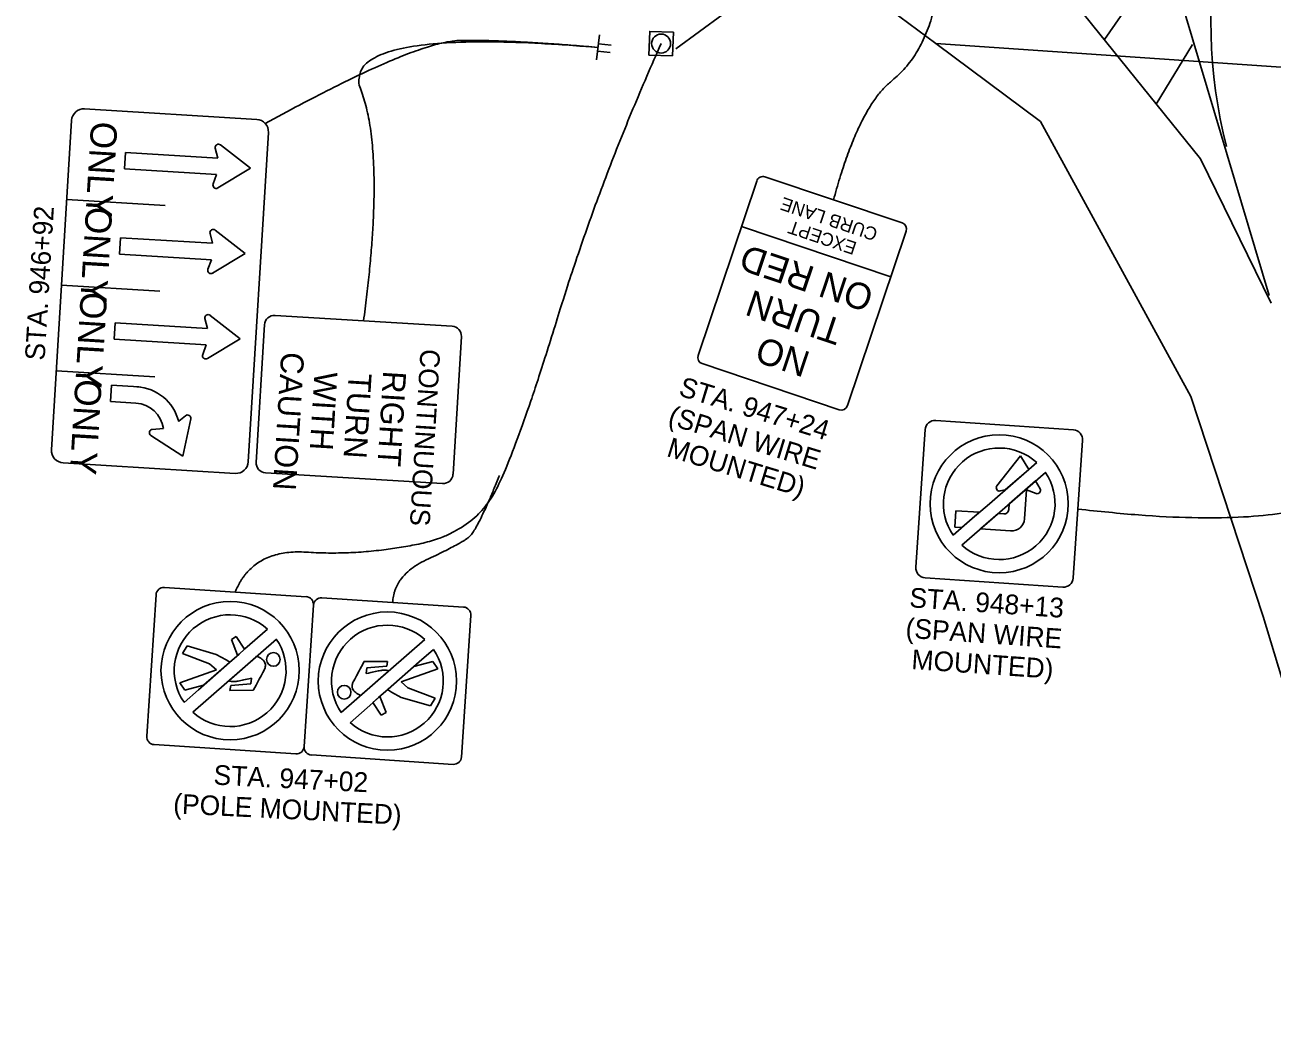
# Model space of a CAD drawing. Extents: x 1847379 to 1850904, y 217032 to 220169.
# Drawn here: x 1848753.2 to 1848911.4, y 218673.2 to 218799.7 of the extents above; entities that cross this region are included whole.
import ezdxf

# ---------------------------------------------------------------- set-up
doc = ezdxf.new("R2010")
doc.units = 0
for name, color, linetype in [('BR_P_Gen_Approach_Slab_Hidden', 7, 'Continuous'), ('BR_P_Gen_Phase_Construction', 7, 'Continuous'), ('PM_P_Channelizing_Line', 7, 'Continuous'), ('PM_P_Dotted_Line', 7, 'Continuous'), ('PM_P_Edge_Line', 7, 'Continuous'), ('PM_P_Transverse_Line', 7, 'Continuous'), ('SG_X_Wiring', 7, 'Continuous'), ('SN_X_Foundation', 7, 'Continuous'), ('SN_X_Public', 7, 'Continuous'), ('SN_X_Text', 7, 'Continuous')]:
    doc.layers.add(name, color=color, linetype=linetype)

msp = doc.modelspace()

# ---------------------------------------------------------------- linework, layer by layer
at = {"layer": 'BR_P_Gen_Approach_Slab_Hidden'}
for p, q in [((1848868.73, 218797.37), (1848882.03, 218787.46)), ((1848882.03, 218787.46), (1848901.06, 218752.58)), ((1848901.06, 218752.58), (1848910.26, 218724.65)), ((1848910.26, 218724.65), (1848925.73, 218673.2))]:
    msp.add_line(p, q, dxfattribs=at)
at = {"layer": 'BR_P_Gen_Phase_Construction'}
msp.add_line((1848868.73, 218797.37), (1848933.64, 218792.93), dxfattribs=at)
at = {"layer": 'PM_P_Channelizing_Line'}
msp.add_lwpolyline([(1848911.03, 218765.37), (1848897.81, 218809.62), (1848893.91, 218821.93), (1848835.25, 218825.52), (1848857.61, 218820.78), (1848883.89, 218805.62), (1848902.29, 218782.73), (1848911.26, 218764.42)], dxfattribs=at)
at = {"layer": 'PM_P_Dotted_Line'}
msp.add_arc((1848965.57, 218799.82), 61.94, 89.125, 194.5243, dxfattribs=at)
at = {"layer": 'PM_P_Edge_Line'}
msp.add_line((1848858.25, 218805.17), (1848868.73, 218797.37), dxfattribs=at)
at = {"layer": 'PM_P_Transverse_Line'}
for p, q in [((1848897.69, 218808.79), (1848890.12, 218797.86)), ((1848896.7, 218789.68), (1848901.29, 218797.25))]:
    msp.add_line(p, q, dxfattribs=at)
at = {"layer": 'SG_X_Wiring'}
msp.add_line((1848847.49, 218805.29), (1848835.76, 218796.68), dxfattribs=at)
at = {"layer": 'SN_X_Foundation'}
msp.add_lwpolyline([(1848835.36, 218795.8), (1848835.47, 218798.79), (1848832.47, 218798.9), (1848832.36, 218795.9)], close=True, dxfattribs=at)
msp.add_circle((1848833.91, 218797.35), 1.2, dxfattribs=at)
at = {"layer": 'SN_X_Public'}
for p, q in [((1848825.73, 218795.28), (1848826.11, 218798.46)), ((1848825.86, 218796.39), (1848827.45, 218796.2)), ((1848825.92, 218796.87), (1848825.92, 218796.87)), ((1848825.98, 218797.34), (1848827.56, 218797.15)), ((1848766, 218783.53), (1848765.87, 218781.45)), ((1848777.68, 218782.82), (1848766, 218783.53)), ((1848777.37, 218784.07), (1848777.68, 218782.82)), ((1848781.84, 218781.53), (1848778.03, 218784.5)), ((1848765.87, 218781.45), (1848777.55, 218780.74)), ((1848777.55, 218780.74), (1848777.1, 218779.54)), ((1848777.7, 218779.03), (1848781.84, 218781.53)), ((1848758.54, 218777.57), (1848771.02, 218776.81)), ((1848844.09, 218774.14), (1848863.05, 218767.77)), ((1848765.34, 218772.72), (1848765.22, 218770.64)), ((1848777.02, 218772.01), (1848765.34, 218772.72)), ((1848776.71, 218773.26), (1848777.02, 218772.01)), ((1848781.18, 218770.71), (1848777.37, 218773.69)), ((1848765.22, 218770.64), (1848776.9, 218769.93)), ((1848776.9, 218769.93), (1848776.44, 218768.73)), ((1848777.04, 218768.22), (1848781.18, 218770.71)), ((1848757.88, 218766.7), (1848770.36, 218765.94)), ((1848764.69, 218761.91), (1848764.56, 218759.83)), ((1848776.37, 218761.2), (1848764.69, 218761.91)), ((1848776.06, 218762.45), (1848776.37, 218761.2)), ((1848780.53, 218759.9), (1848776.72, 218762.87)), ((1848764.56, 218759.83), (1848776.24, 218759.12)), ((1848776.38, 218757.41), (1848780.53, 218759.9)), ((1848776.24, 218759.12), (1848775.78, 218757.91)), ((1848757.22, 218755.84), (1848769.7, 218755.08)), ((1848764.08, 218751.92), (1848764.21, 218754)), ((1848764.21, 218754), (1848767.7, 218753.79)), ((1848767.7, 218753.79), (1848767.43, 218753.81)), ((1848767.31, 218751.73), (1848764.08, 218751.92)), ((1848772.74, 218749.43), (1848773.59, 218750.14)), ((1848774.27, 218749.73), (1848773.26, 218745)), ((1848773.26, 218745), (1848769.2, 218747.64)), ((1848769.39, 218748.4), (1848770.79, 218748.53)), ((1848876.49, 218741.25), (1848879.5, 218745.04)), ((1848879.5, 218745.04), (1848876.49, 218741.25)), ((1848880.52, 218743.32), (1848879.5, 218745.04)), ((1848880.52, 218743.32), (1848879.5, 218745.04)), ((1848882.63, 218742.95), (1848872.03, 218733.71)), ((1848877.55, 218740.73), (1848880.52, 218743.32)), ((1848881.38, 218741.86), (1848878.04, 218738.94)), ((1848881.96, 218740.88), (1848881.38, 218741.86)), ((1848881.96, 218740.88), (1848881.38, 218741.86)), ((1848876.92, 218740.59), (1848877.54, 218740.74)), ((1848876.92, 218740.59), (1848877.54, 218740.74)), ((1848880, 218737.07), (1848880.25, 218740.74)), ((1848880, 218737.07), (1848880.25, 218740.74)), ((1848881.45, 218740.28), (1848880.25, 218740.74)), ((1848880.25, 218740.74), (1848881.45, 218740.28)), ((1848871.15, 218736), (1848871.3, 218738.08)), ((1848871.3, 218738.08), (1848871.15, 218736)), ((1848874.28, 218737.88), (1848871.3, 218738.08)), ((1848874.28, 218737.88), (1848871.3, 218738.08)), ((1848873.37, 218737.09), (1848874.28, 218737.88)), ((1848876.63, 218737.72), (1848874.47, 218735.83)), ((1848877.35, 218737.67), (1848876.63, 218737.72)), ((1848877.35, 218737.67), (1848876.63, 218737.72)), ((1848877.99, 218738.22), (1848878.04, 218738.94)), ((1848878.04, 218738.94), (1848877.99, 218738.22)), ((1848872.06, 218735.94), (1848873.37, 218737.09)), ((1848872.06, 218735.94), (1848871.15, 218736)), ((1848871.15, 218736), (1848872.06, 218735.94)), ((1848874.47, 218735.83), (1848874.41, 218735.78)), ((1848878.22, 218735.52), (1848874.41, 218735.78)), ((1848874.41, 218735.78), (1848878.22, 218735.52)), ((1848780.04, 218722.12), (1848779.43, 218721.76)), ((1848780.04, 218722.12), (1848779.43, 218721.76)), ((1848781.09, 218720.51), (1848780.04, 218722.12)), ((1848781.09, 218720.51), (1848780.04, 218722.12)), ((1848773.79, 218720.94), (1848773.21, 218719.95)), ((1848773.79, 218720.94), (1848773.21, 218719.95)), ((1848777.5, 218719.86), (1848773.79, 218720.94)), ((1848777.5, 218719.86), (1848773.79, 218720.94)), ((1848785.12, 218721.79), (1848774.52, 218712.52)), ((1848779.43, 218721.76), (1848780.21, 218719.74)), ((1848779.43, 218721.76), (1848780.21, 218719.74)), ((1848793.34, 218712.46), (1848803.94, 218721.74)), ((1848773.21, 218719.95), (1848776.66, 218718.67)), ((1848773.21, 218719.95), (1848776.66, 218718.67)), ((1848775.89, 218715.95), (1848779.17, 218718.83)), ((1848776.66, 218718.67), (1848777.52, 218717.9)), ((1848776.66, 218718.67), (1848777.52, 218717.9)), ((1848778.74, 218719.18), (1848777.5, 218719.86)), ((1848778.74, 218719.18), (1848777.5, 218719.86)), ((1848779.24, 218718.88), (1848778.74, 218719.18)), ((1848779.24, 218718.88), (1848778.74, 218719.18)), ((1848782.51, 218719.51), (1848779.09, 218716.51)), ((1848779.17, 218718.83), (1848779.24, 218718.88)), ((1848780.21, 218719.74), (1848780.39, 218719.89)), ((1848782.62, 218719.61), (1848782.51, 218719.51)), ((1848799.23, 218718.97), (1848796.23, 218718.94)), ((1848799.23, 218718.97), (1848796.23, 218718.94)), ((1848796.23, 218718.94), (1848796.23, 218718.92)), ((1848796.23, 218718.94), (1848796.23, 218718.92)), ((1848799.13, 218718.34), (1848799.23, 218718.97)), ((1848799.13, 218718.34), (1848799.23, 218718.97)), ((1848804.96, 218718.95), (1848802.57, 218718.31)), ((1848804.96, 218718.95), (1848802.57, 218718.31)), ((1848805.58, 218718.03), (1848804.96, 218718.95)), ((1848805.58, 218718.03), (1848804.96, 218718.95)), ((1848777.52, 218717.9), (1848772.88, 218716.23)), ((1848777.52, 218717.9), (1848772.88, 218716.23)), ((1848795.95, 218714.75), (1848799.37, 218717.75)), ((1848796.5, 218717.41), (1848796.58, 218718.14)), ((1848796.5, 218717.41), (1848796.58, 218718.14)), ((1848796.58, 218718.14), (1848799.13, 218718.34)), ((1848796.58, 218718.14), (1848799.13, 218718.34)), ((1848802.57, 218718.31), (1848799.29, 218715.43)), ((1848800.94, 218716.36), (1848805.58, 218718.03)), ((1848800.94, 218716.36), (1848805.58, 218718.03)), ((1848772.88, 218716.23), (1848773.5, 218715.3)), ((1848772.88, 218716.23), (1848773.5, 218715.3)), ((1848773.5, 218715.3), (1848775.89, 218715.95)), ((1848773.5, 218715.3), (1848775.89, 218715.95)), ((1848779.33, 218715.92), (1848779.23, 218715.29)), ((1848779.33, 218715.92), (1848779.23, 218715.29)), ((1848781.88, 218716.12), (1848779.33, 218715.92)), ((1848781.88, 218716.12), (1848779.33, 218715.92)), ((1848781.96, 218716.85), (1848781.88, 218716.12)), ((1848781.96, 218716.85), (1848781.88, 218716.12)), ((1848801.8, 218715.59), (1848800.94, 218716.36)), ((1848801.8, 218715.59), (1848800.94, 218716.36)), ((1848805.25, 218714.31), (1848801.8, 218715.59)), ((1848805.25, 218714.31), (1848801.8, 218715.59)), ((1848779.23, 218715.29), (1848782.23, 218715.32)), ((1848779.23, 218715.29), (1848782.23, 218715.32)), ((1848782.23, 218715.32), (1848782.23, 218715.34)), ((1848782.23, 218715.32), (1848782.23, 218715.34)), ((1848795.84, 218714.65), (1848795.95, 218714.75)), ((1848798.25, 218714.52), (1848798.07, 218714.37)), ((1848799.03, 218712.5), (1848798.25, 218714.52)), ((1848799.03, 218712.5), (1848798.25, 218714.52)), ((1848799.29, 218715.43), (1848799.23, 218715.38)), ((1848799.23, 218715.38), (1848799.72, 218715.08)), ((1848799.23, 218715.38), (1848799.72, 218715.08)), ((1848799.72, 218715.08), (1848800.96, 218714.4)), ((1848799.72, 218715.08), (1848800.96, 218714.4)), ((1848800.96, 218714.4), (1848804.67, 218713.32)), ((1848800.96, 218714.4), (1848804.67, 218713.32)), ((1848804.67, 218713.32), (1848805.25, 218714.31)), ((1848804.67, 218713.32), (1848805.25, 218714.31)), ((1848797.37, 218713.75), (1848798.42, 218712.14)), ((1848797.37, 218713.75), (1848798.42, 218712.14)), ((1848798.42, 218712.14), (1848799.03, 218712.5)), ((1848798.42, 218712.14), (1848799.03, 218712.5))]:
    msp.add_line(p, q, dxfattribs=at)
for points in [[(1848760.81, 218789.07), (1848782.64, 218787.74)], [(1848756.61, 218745.8), (1848759.15, 218787.6)], [(1848784.11, 218786.08), (1848781.56, 218744.29)], [(1848864.46, 218774.6), (1848847.08, 218780.44)], [(1848846.03, 218779.91), (1848838.6, 218757.79)], [(1848857.56, 218751.43), (1848864.99, 218773.54)], [(1848783.62, 218761.69), (1848782.56, 218744.22)], [(1848807.41, 218761.49), (1848784.95, 218762.86)], [(1848807.52, 218742.7), (1848808.58, 218760.17)], [(1848839.12, 218756.74), (1848856.5, 218750.9)], [(1848868.74, 218749.53), (1848886.2, 218748.34)], [(1848866.21, 218730.91), (1848867.41, 218748.37)], [(1848887.36, 218747.01), (1848886.16, 218729.55)], [(1848779.91, 218742.82), (1848758.07, 218744.15)], [(1848881.54, 218744.21), (1848875.53, 218738.97), (1848873.37, 218737.09)], [(1848783.73, 218742.9), (1848806.19, 218741.53)], [(1848877.54, 218740.74), (1848877.55, 218740.73)], [(1848873.37, 218737.09), (1848870.94, 218734.96)], [(1848788.89, 218727.17), (1848770.93, 218728.36)], [(1848884.83, 218728.38), (1848867.37, 218729.58)], [(1848769.87, 218727.43), (1848768.68, 218709.47)], [(1848808.85, 218725.86), (1848790.89, 218727.04)], [(1848789.82, 218726.11), (1848788.64, 218708.15)], [(1848788.64, 218708.15), (1848789.82, 218726.11)], [(1848808.59, 218706.83), (1848809.78, 218724.79)], [(1848784, 218723.06), (1848781.12, 218720.54), (1848780.39, 218719.89), (1848780.39, 218719.89)], [(1848780.39, 218719.89), (1848781.09, 218720.51), (1848781.09, 218720.51)], [(1848798.07, 218714.37), (1848799.29, 218715.43), (1848803.23, 218718.89), (1848805.04, 218720.49)], [(1848780.39, 218719.89), (1848779.17, 218718.83), (1848775.23, 218715.37), (1848773.42, 218713.77)], [(1848782.51, 218719.51), (1848782.51, 218719.51)], [(1848794.46, 218711.19), (1848797.34, 218713.72), (1848798.07, 218714.37), (1848798.07, 218714.37)], [(1848795.95, 218714.75), (1848795.95, 218714.75)], [(1848798.07, 218714.37), (1848797.37, 218713.75), (1848797.37, 218713.75)], [(1848769.61, 218708.4), (1848787.57, 218707.22)], [(1848789.57, 218707.09), (1848807.53, 218705.9)]]:
    msp.add_lwpolyline(points, dxfattribs=at)
for centre, radius in [((1848876.78, 218738.96), 8.75), ((1848779.26, 218717.79), 8.77), ((1848799.2, 218716.47), 8.77), ((1848784.74, 218719.21), 0.864), ((1848793.72, 218715.05), 0.864)]:
    msp.add_circle(centre, radius, dxfattribs=at)
for centre, radius, start, end in [((1848760.71, 218787.51), 1.56, 86.5194, 176.5194), ((1848782.55, 218786.18), 1.56, 356.5194, 86.5194), ((1848777.78, 218784.17), 0.417, 52.0031, 193.8812), ((1848846.82, 218779.65), 0.833, 71.436, 161.436), ((1848777.49, 218779.39), 0.417, 159.1575, 301.0356), ((1848864.2, 218773.81), 0.833, 341.436, 71.436), ((1848777.12, 218773.36), 0.417, 52.0031, 193.8812), ((1848776.83, 218768.58), 0.417, 159.1575, 301.0356), ((1848776.46, 218762.55), 0.417, 52.0031, 193.8812), ((1848784.87, 218761.61), 1.25, 86.5194, 176.5194), ((1848807.33, 218760.25), 1.25, 356.5194, 86.5194), ((1848776.17, 218757.76), 0.417, 159.1575, 301.0356), ((1848839.39, 218757.53), 0.833, 161.436, 251.436), ((1848767.08, 218747.98), 5.84, 14.2874, 86.5194), ((1848767.08, 218747.98), 3.75, 8.2961, 86.5194), ((1848856.77, 218751.69), 0.833, 251.436, 341.436), ((1848773.86, 218749.82), 0.417, 347.9796, 129.8577), ((1848868.65, 218748.29), 1.25, 86.0842, 176.0842), ((1848769.43, 218747.99), 0.417, 95.134, 237.0121), ((1848886.11, 218747.09), 1.25, 356.0842, 86.0842), ((1848758.17, 218745.71), 1.56, 176.5194, 266.5194), ((1848876.78, 218738.96), 7.08, 47.8405, 214.3278), ((1848876.78, 218738.96), 7.08, 47.8405, 214.3278), ((1848780, 218744.38), 1.56, 266.5194, 356.5194), ((1848783.81, 218744.14), 1.25, 176.5194, 266.5194), ((1848806.27, 218742.78), 1.25, 266.5194, 356.5194), ((1848876.78, 218738.96), 7.08, 227.8405, 34.3278), ((1848876.82, 218740.99), 0.417, 141.5679, 283.446), ((1848876.82, 218740.99), 0.417, 141.5679, 283.446), ((1848881.6, 218740.66), 0.417, 248.7223, 30.6004), ((1848881.6, 218740.66), 0.417, 248.7223, 30.6004), ((1848877.39, 218738.27), 0.6, 266.0842, 356.0842), ((1848877.39, 218738.27), 0.6, 266.0842, 356.0842), ((1848878.33, 218737.18), 1.67, 266.0842, 356.0842), ((1848878.33, 218737.18), 1.67, 266.0842, 356.0842), ((1848867.46, 218730.83), 1.25, 176.0842, 266.0842), ((1848770.86, 218727.36), 1, 86.2275, 176.2275), ((1848884.92, 218729.63), 1.25, 266.0842, 356.0842), ((1848788.82, 218726.18), 1, 356.2275, 86.2275), ((1848790.82, 218726.04), 1, 86.2275, 176.2275), ((1848808.78, 218724.86), 1, 356.2275, 86.2275), ((1848779.26, 218717.79), 7.09, 48.0755, 214.4755), ((1848779.26, 218717.79), 7.09, 48.0755, 214.4755), ((1848799.2, 218716.47), 7.09, 48.0466, 214.3989), ((1848779.26, 218717.79), 7.09, 228.0466, 34.3989), ((1848799.2, 218716.47), 7.09, 228.0755, 34.4755), ((1848799.2, 218716.47), 7.09, 228.0755, 34.4755), ((1848769.68, 218709.4), 1, 176.2275, 266.2275), ((1848787.64, 218708.22), 1, 266.2275, 356.2275), ((1848789.64, 218708.08), 1, 176.2275, 266.2275), ((1848807.6, 218706.9), 1, 266.2275, 356.2275)]:
    msp.add_arc(centre, radius, start, end, dxfattribs=at)
for points, degree in [([(1848949.85, 218847.48), (1848938.73, 218843.63), (1848921.54, 218831.73), (1848922.68, 218757.56), (1848923.54, 218734.09), (1848886.76, 218738.28)], 2), ([(1848858.62, 218806.34), (1848864.01, 218810.35), (1848870.11, 218808.95), (1848867.24, 218795.89), (1848858.93, 218789.23), (1848855.77, 218777.52)], 2), ([(1848825.92, 218796.87), (1848813.93, 218797.89), (1848802.56, 218797.57), (1848783.72, 218787.21)], 2), ([(1848833.91, 218797.35), (1848826.08, 218779.83), (1848815.84, 218746.47), (1848810.24, 218735.28), (1848795.81, 218732.37), (1848782.14, 218733.27), (1848779.91, 218727.77)], 2), ([(1848825.92, 218796.87), (1848792.71, 218799.65), (1848799, 218783.16), (1848796.18, 218762.18)], 2), ([(1848799.87, 218726.45), (1848800.05, 218729.96), (1848808.45, 218733.86), (1848810.6, 218735.57), (1848813.42, 218742.57)], 2), ([(1848782.23, 218715.34), (1848782.68, 218716.19), (1848783.4, 218717.54), (1848783.67, 218718.03), (1848783.71, 218718.2), (1848783.72, 218718.37), (1848783.75, 218718.77), (1848783.31, 218719.3), (1848782.88, 218719.49), (1848782.62, 218719.61)], 3), ([(1848782.23, 218715.34), (1848782.68, 218716.19), (1848783.4, 218717.54), (1848783.67, 218718.03), (1848783.71, 218718.2), (1848783.72, 218718.37), (1848783.75, 218718.77), (1848783.31, 218719.3), (1848782.88, 218719.49), (1848782.62, 218719.61)], 3), ([(1848796.23, 218718.92), (1848795.78, 218718.07), (1848795.06, 218716.72), (1848794.79, 218716.23), (1848794.75, 218716.06), (1848794.74, 218715.89), (1848794.71, 218715.49), (1848795.15, 218714.96), (1848795.58, 218714.77), (1848795.84, 218714.65)], 3), ([(1848796.23, 218718.92), (1848795.78, 218718.07), (1848795.06, 218716.72), (1848794.79, 218716.23), (1848794.75, 218716.06), (1848794.74, 218715.89), (1848794.71, 218715.49), (1848795.15, 218714.96), (1848795.58, 218714.77), (1848795.84, 218714.65)], 3), ([(1848799.37, 218717.75), (1848799.31, 218717.79), (1848799.11, 218717.86), (1848798.65, 218717.86), (1848798.23, 218717.8), (1848797.49, 218717.65), (1848796.98, 218717.53), (1848796.5, 218717.41)], 3), ([(1848799.37, 218717.75), (1848799.31, 218717.79), (1848799.11, 218717.86), (1848798.65, 218717.86), (1848798.23, 218717.8), (1848797.49, 218717.65), (1848796.98, 218717.53), (1848796.5, 218717.41)], 3), ([(1848779.09, 218716.51), (1848779.15, 218716.47), (1848779.35, 218716.4), (1848779.81, 218716.4), (1848780.23, 218716.46), (1848780.97, 218716.61), (1848781.48, 218716.73), (1848781.96, 218716.85)], 3), ([(1848779.09, 218716.51), (1848779.15, 218716.47), (1848779.35, 218716.4), (1848779.81, 218716.4), (1848780.23, 218716.46), (1848780.97, 218716.61), (1848781.48, 218716.73), (1848781.96, 218716.85)], 3)]:
    msp.add_open_spline(points, degree=degree, dxfattribs=at)

# ---------------------------------------------------------------- texts
for s, height, rotation, p in [('ONLY', 3.333, 266.5194, (1848761.65, 218787.53)), ('CURB LANE', 1.667, 161.436, (1848861.5, 218773.84)), ('STA. 946+92', 2.5, 86.5194, (1848755.73, 218757.09)), ('ONLY', 3.333, 266.5194, (1848761, 218776.72)), ('EXCEPT', 1.667, 161.436, (1848858.84, 218772.09)), ('ON RED', 3.333, 161.436, (1848861.08, 218766.39)), ('ONLY', 3.333, 266.5194, (1848760.34, 218765.91)), ('TURN', 3.333, 161.436, (1848857.19, 218762.21)), ('NO', 3.333, 161.436, (1848853.01, 218758.12)), ('CONTINUOUS', 2.5, 266.5194, (1848803.41, 218758.65)), ('CAUTION', 2.915, 266.5194, (1848785.75, 218758.27)), ('WITH', 2.915, 266.5194, (1848789.96, 218755.77)), ('TURN', 2.915, 266.5194, (1848794.3, 218755.61)), ('RIGHT', 2.915, 266.5194, (1848798.68, 218755.88)), ('ONLY', 3.333, 266.5194, (1848759.66, 218754.85))]:
    msp.add_text(s, height=height, rotation=rotation, dxfattribs=at).set_placement(p)
at = {"layer": 'SN_X_Text'}
for s, rotation, p in [('STA. 947+24', 343.0107, (1848836.01, 218752.73)), ('(SPAN WIRE ', 343.0107, (1848834.64, 218749.07)), ('MOUNTED)', 343.0107, (1848834.48, 218745.04)), ('STA. 948+13', 356.0516, (1848865.33, 218725.84)), ('(SPAN WIRE ', 356.0516, (1848864.85, 218721.97)), ('MOUNTED)', 356.0516, (1848865.6, 218718)), ('STA. 947+02', 357.1372, (1848777.11, 218703.34)), ('(POLE MOUNTED)', 357.1372, (1848772, 218699.69))]:
    msp.add_text(s, height=2.5, rotation=rotation, dxfattribs=at).set_placement(p)

doc.saveas('drawing.dxf')
